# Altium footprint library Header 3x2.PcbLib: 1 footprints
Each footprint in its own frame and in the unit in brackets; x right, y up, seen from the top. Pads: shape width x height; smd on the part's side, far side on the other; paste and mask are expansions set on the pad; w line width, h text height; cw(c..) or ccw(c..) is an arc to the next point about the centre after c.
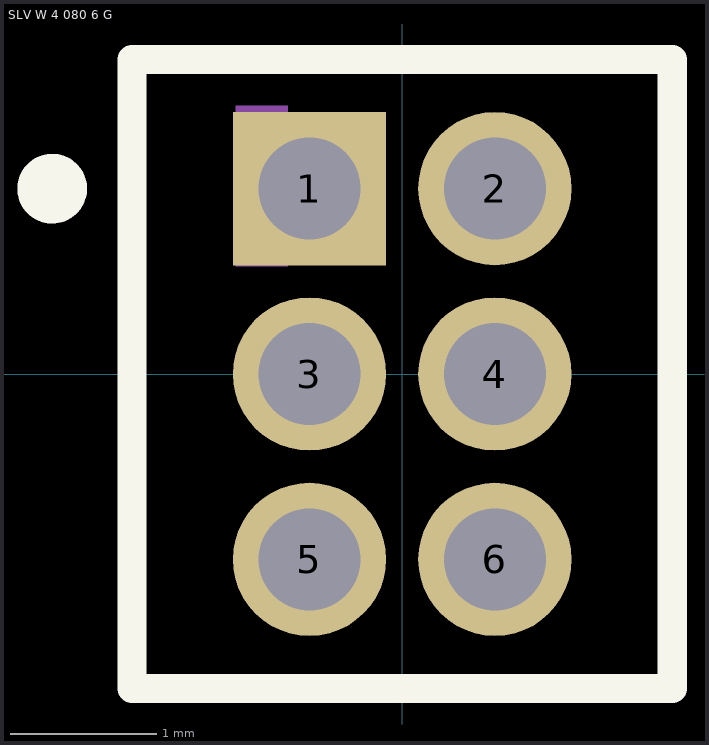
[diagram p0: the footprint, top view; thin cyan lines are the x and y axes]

## SLV W 4 080 6 G [mm] "Sullins"
height 4
pads (6):
  rect 1.05x1.05 hole 0.7 paste+0: 1(-0.635,1.27)
  round 1.05 hole 0.7 paste+0: 2(0.635,1.27) 3(-0.635,0) 4(0.635,0) 5(-0.635,-1.27) 6(0.635,-1.27)
Top Overlay:
  circle w0.254: c-2.398,1.27 r0.112
  lines w0.2: -1.85,-2.155 -1.85,2.155 1.85,2.155 1.85,-2.155 -1.85,-2.155
M5 Assembly Top:
  rectangle: -1.143,0.735 -0.783,1.839
  lines w0.1: -1.85,-2.155 -1.85,2.155 1.85,2.155 1.85,-2.155 -1.85,-2.155
  text ".Designator" at -1.397,-0.377 h0.76
3D body: height 1.01, standoff 1, extent -1.474,1.083 -1.076,1.482
3D body: height 12.2, standoff -2.5, extent -0.835,1.07 -0.435,1.47
3D body: height 12.2, standoff -2.5, extent -0.835,-0.2 -0.435,0.2
3D body: height 12.2, standoff -2.5, extent -0.835,-1.47 -0.435,-1.07
3D body: height 12.2, standoff -2.5, extent 0.435,1.07 0.835,1.47
3D body: height 12.2, standoff -2.5, extent 0.435,-0.2 0.835,0.2
3D body: height 12.2, standoff -2.5, extent 0.435,-1.47 0.835,-1.07
3D body: height 1, standoff 0, extent -1.85,-2.155 1.85,2.155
